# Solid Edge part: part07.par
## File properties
Author: CADCIM
Template: Normal.par
Last saved by: TIET
Revision: 5
Application: Solid Edge
Accuracy: 0.99
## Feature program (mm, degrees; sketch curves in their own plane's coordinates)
sketch for "unnamed Protrusion 1" #1 plane through (0, 0, 0) normal (0, 0, 1) x-axis (1, 0, 0)
  circle centre (17.5, 12.5) radius 2.5
sketch for "unnamed Protrusion 1" #2 plane through (0, 0, 0) normal (0, 0, 1) x-axis (1, 0, 0)
  circle centre (17.5, -12.5) radius 2.5
sketch for "unnamed Protrusion 1" #3 plane through (0, 0, 0) normal (0, 0, 1) x-axis (1, 0, 0)
  line (-17.5, 2.5) -> (-22.5, 2.5)
  line (-22.5, 2.5) -> (-22.5, 5.5)
  arc centre (-20.5, 5.5) radius 2 from (-22.5, 5.5) to (-20.5, 7.5) cw
  line (-20.5, 7.5) -> (10.5, 7.5)
  arc centre (10.5, 9.5) radius 2 from (10.5, 7.5) to (12.5, 9.5) ccw
  line (12.5, 9.5) -> (12.5, 12.5)
  arc centre (17.5, 12.5) radius 5 from (12.5, 12.5) to (22.5, 12.5) cw
  line (22.5, 12.5) -> (22.5, -12.5)
  arc centre (17.5, -12.5) radius 5 from (12.5, -12.5) to (22.5, -12.5) ccw
  line (12.5, -9.5) -> (12.5, -12.5)
  arc centre (10.5, -9.5) radius 2 from (10.5, -7.5) to (12.5, -9.5) cw
  line (-20.5, -7.5) -> (10.5, -7.5)
  arc centre (-20.5, -5.5) radius 2 from (-22.5, -5.5) to (-20.5, -7.5) ccw
  line (-22.5, -2.5) -> (-22.5, -5.5)
  line (-17.5, -2.5) -> (-22.5, -2.5)
  arc centre (-17.5, 0) radius 2.5 from (-17.5, 2.5) to (-17.5, -2.5) cw
  dimension (linear) = 22.5
  dimension (linear) = 17.5
extrude "unnamed Protrusion 1" add finite 5 along +normal
sketch for "ExtrudedProtrusion_2" #1 plane through (6.5901, 0, 20.9099) normal (0.707107, 0, 0.707107) x-axis (0, 1, 0)
  circle centre (0, -5.5) radius 3.75
sketch for "ExtrudedProtrusion_2" #2 plane through (6.5901, 0, 20.9099) normal (0.707107, 0, 0.707107) x-axis (0, 1, 0)
  line (-7.5, -22.5) -> (-7.5, -5.5)
  arc centre (0, -5.5) radius 7.5 from (7.5, -5.5) to (-7.5, -5.5) ccw
  line (7.5, -5.5) -> (7.5, -22.5)
  line (7.5, -22.5) -> (-7.5, -22.5)
  dimension (linear) = 7.5
extrude "ExtrudedProtrusion_2" add through along -normal
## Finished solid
Body 1: solid body, 26 faces, 64 edges, 38 vertices.
  Faces by surface: plane 15, cylinder 11
  Edges by curve: line 42, circle 20, ellipse 2
Bounding box of the edges (mm): 45.000 x 35.000 x 22.324, from (-22.5, -17.5, 0) to (22.5, 17.5, 22.3241).
Cylindrical faces by radius (mm): R2 x4, R2.5 x3, R3.75 x1, R5 x2, R7.5 x1
Planar faces by outward normal: +x 1, +y 2, +z 4, -x 4, -y 2, -z 1, oblique 1
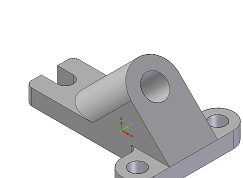
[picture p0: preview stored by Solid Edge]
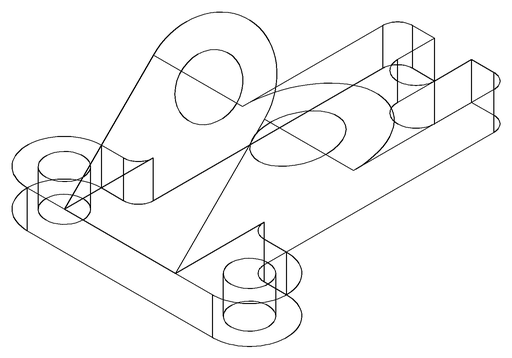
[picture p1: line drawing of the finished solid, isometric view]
